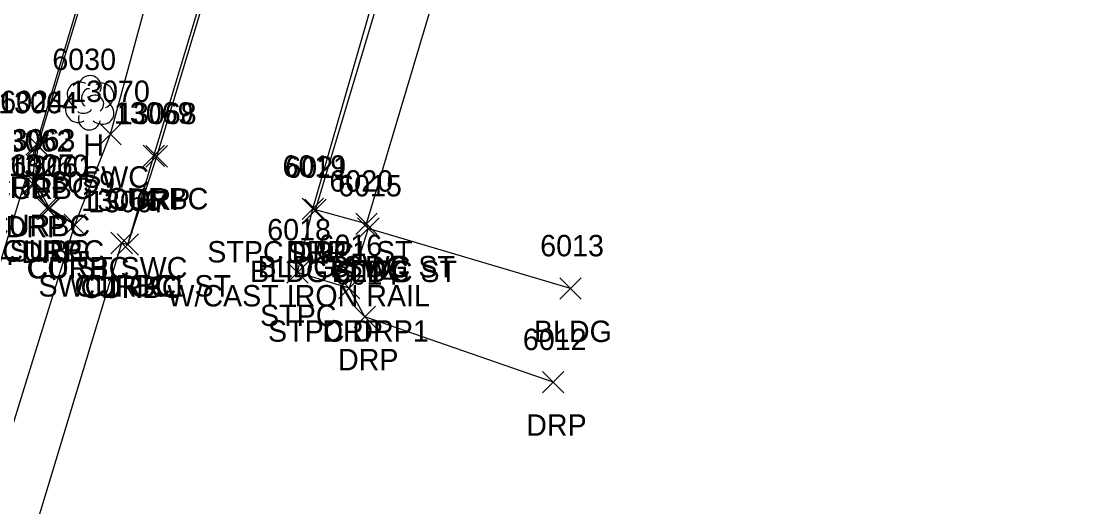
# Model space of a CAD drawing. Extents: x 1462089 to 1464015, y 730534 to 736144.
# Drawn here: x 1462484 to 1462582.3, y 730885.2 to 730930.6 of the extents above; entities that cross this region are included whole.
import ezdxf

# ---------------------------------------------------------------- set-up
doc = ezdxf.new("R2010")
doc.units = 0
for name, color, linetype in [('L_A', 7, 'Continuous'), ('L_I', 7, 'Continuous'), ('L_TIC', 7, 'Continuous'), ('LBC', 7, 'Continuous'), ('LBF', 7, 'Continuous'), ('LTD', 7, 'Continuous'), ('P_A', 7, 'Continuous'), ('P_I', 7, 'Continuous'), ('P_TIC', 7, 'Continuous'), ('PET', 7, 'Continuous'), ('R_A', 7, 'Continuous'), ('R_C', 7, 'Continuous'), ('R_I', 7, 'Continuous'), ('R_TIC', 7, 'Continuous'), ('RC', 7, 'Continuous'), ('RDP', 7, 'Continuous'), ('RSW', 7, 'Continuous'), ('U_A', 7, 'Continuous'), ('U_I', 7, 'Continuous'), ('U_TIC', 7, 'Continuous')]:
    doc.layers.add(name, color=color, linetype=linetype)

msp = doc.modelspace()

# ---------------------------------------------------------------- linework, layer by layer
at = {"layer": 'L_TIC'}
for points in [[(1462510.272, 730912.038), (1462512.272, 730914.038)], [(1462512.272, 730912.038), (1462510.272, 730914.038)], [(1462515.298, 730910.649), (1462517.298, 730912.649)], [(1462517.298, 730910.649), (1462515.298, 730912.649)], [(1462515.458, 730910.205), (1462517.458, 730912.205)], [(1462517.458, 730910.205), (1462515.458, 730912.205)], [(1462515.458, 730910.205), (1462517.458, 730912.205)], [(1462517.458, 730910.205), (1462515.458, 730912.205)], [(1462508.84, 730906.104), (1462510.84, 730908.104)], [(1462510.84, 730906.104), (1462508.84, 730908.104)], [(1462513.683, 730904.64), (1462515.683, 730906.64)], [(1462515.683, 730904.64), (1462513.683, 730906.64)], [(1462534.326, 730904.613), (1462536.326, 730906.613)], [(1462536.326, 730904.613), (1462534.326, 730906.613)]]:
    msp.add_lwpolyline(points, dxfattribs=at)
at = {"layer": 'LBC'}
msp.add_lwpolyline([(1462535.326, 730905.613), (1462516.458, 730911.205), (1462516.298, 730911.649), (1462524.384, 730938.78), (1462533.922, 730970.766), (1462531.573, 730971.668), (1462537.417, 730991.493), (1462540.657, 731001.604), (1462560.129, 730995.57)], dxfattribs=at)
at = {"layer": 'LBF'}
msp.add_lwpolyline([(1462516.458, 730911.205), (1462514.683, 730905.64), (1462509.84, 730907.104), (1462511.272, 730913.038)], dxfattribs=at)
at = {"layer": 'LTD'}
msp.add_line((1462490.429, 730922.994), (1462490.429, 730922.994), dxfattribs=at)
msp.add_line((1462490.429, 730922.994), (1462490.429, 730922.994), dxfattribs=at)
msp.add_arc((1462490.476, 730924.428), 1.047, 335.52715, 180.95627, dxfattribs=at)
for centre, major_axis, ratio, start_param, end_param in [((1462489.638, 730923.661), (1.21, -0.512), 0.895232, 1.570796, 4.712389), ((1462490.221, 730923.452), (-0.208, -0.792), 0.645439, 3.141593, 6.283185), ((1462491.471, 730923.578), (-1.141, -0.483), 0.949671, 1.570796, 4.712389), ((1462489.346, 730922.286), (0.584, -1.042), 0.959034, 3.141593, 6.283185), ((1462490.93, 730922.827), (-0.5, 0.667), 0.989748, 3.141593, 6.283185), ((1462491.43, 730922.161), (-1.09, 0.792), 0.841452, 1.570796, 4.712389), ((1462489.971, 730922.244), (-0.625, -0.083), 0.423636, 0, 3.141593), ((1462490.43, 730921.494), (0.265, 1.061), 0.942809, 1.570796, 4.712389)]:
    msp.add_ellipse(centre, major_axis=major_axis, ratio=ratio, start_param=start_param, end_param=end_param, dxfattribs=at)
at = {"layer": 'P_TIC'}
for points in [[(1462484.477, 730918.066), (1462486.477, 730920.066)], [(1462486.477, 730918.066), (1462484.477, 730920.066)]]:
    msp.add_lwpolyline(points, dxfattribs=at)
at = {"layer": 'PET'}
msp.add_lwpolyline([(1462373.445, 730550.573), (1462388.309, 730598.891), (1462401.963, 730641.783), (1462433.168, 730744.632), (1462438.196, 730760.147), (1462452.976, 730810.554), (1462463.625, 730846.159), (1462471.864, 730873.588), (1462478.576, 730896.599), (1462485.477, 730919.066), (1462495.517, 730952.686), (1462508.095, 730994.119), (1462517.419, 731025.054), (1462526.796, 731054.959), (1462537.856, 731087.551), (1462549.797, 731117.253), (1462553.734, 731129.646)], dxfattribs=at)
at = {"layer": 'R_TIC'}
for points in [[(1462491.382, 730919.018), (1462493.382, 730921.018)], [(1462493.382, 730919.018), (1462491.382, 730921.018)], [(1462484.617, 730917.96), (1462486.617, 730919.96)], [(1462486.617, 730917.96), (1462484.617, 730919.96)], [(1462495.432, 730916.994), (1462497.432, 730918.994)], [(1462497.432, 730916.994), (1462495.432, 730918.994)], [(1462495.703, 730916.944), (1462497.703, 730918.944)], [(1462497.703, 730916.944), (1462495.703, 730918.944)], [(1462484.115, 730914.389), (1462486.115, 730916.389)], [(1462486.115, 730914.389), (1462484.115, 730916.389)], [(1462484.39, 730914.486), (1462486.39, 730916.486)], [(1462486.39, 730914.486), (1462484.39, 730916.486)], [(1462485.579, 730912.004), (1462487.579, 730914.004)], [(1462487.579, 730912.004), (1462485.579, 730914.004)], [(1462485.707, 730912.107), (1462487.707, 730914.107)], [(1462487.707, 730912.107), (1462485.707, 730914.107)], [(1462510.272, 730912.038), (1462512.272, 730914.038)], [(1462512.272, 730912.038), (1462510.272, 730914.038)], [(1462510.522, 730911.936), (1462512.522, 730913.936)], [(1462512.522, 730911.936), (1462510.522, 730913.936)], [(1462488.057, 730910.55), (1462490.057, 730912.55)], [(1462490.057, 730910.55), (1462488.057, 730912.55)], [(1462488.057, 730910.55), (1462490.057, 730912.55)], [(1462490.057, 730910.55), (1462488.057, 730912.55)], [(1462488.057, 730910.55), (1462490.057, 730912.55)], [(1462490.057, 730910.55), (1462488.057, 730912.55)], [(1462515.298, 730910.649), (1462517.298, 730912.649)], [(1462517.298, 730910.649), (1462515.298, 730912.649)], [(1462492.434, 730908.857), (1462494.434, 730910.857)], [(1462494.434, 730908.857), (1462492.434, 730910.857)], [(1462492.434, 730908.857), (1462494.434, 730910.857)], [(1462494.434, 730908.857), (1462492.434, 730910.857)], [(1462493.015, 730908.723), (1462495.015, 730910.723)], [(1462495.015, 730908.723), (1462493.015, 730910.723)], [(1462493.015, 730908.723), (1462495.015, 730910.723)], [(1462495.015, 730908.723), (1462493.015, 730910.723)], [(1462513.683, 730904.64), (1462515.683, 730906.64)], [(1462515.683, 730904.64), (1462513.683, 730906.64)], [(1462515.143, 730901.972), (1462517.143, 730903.972)], [(1462517.143, 730901.972), (1462515.143, 730903.972)], [(1462532.706, 730895.863), (1462534.706, 730897.863)], [(1462534.706, 730895.863), (1462532.706, 730897.863)]]:
    msp.add_lwpolyline(points, dxfattribs=at)
at = {"layer": 'RC'}
for points in [[(1462493.434, 730909.857), (1462494.015, 730909.723), (1462496.432, 730917.994), (1462504.726, 730945.42), (1462507.323, 730953.276), (1462506.792, 730953.446)], [(1462485.617, 730918.96), (1462495.777, 730952.455)], [(1462489.057, 730911.55), (1462486.707, 730913.107), (1462485.39, 730915.486), (1462485.617, 730918.96)]]:
    msp.add_lwpolyline(points, dxfattribs=at)
at = {"layer": 'RDP'}
for points in [[(1462494.015, 730909.723), (1462496.703, 730917.944), (1462504.987, 730945.36), (1462507.323, 730953.276)], [(1462511.272, 730913.038), (1462518.156, 730936.915)], [(1462485.115, 730915.389), (1462485.477, 730919.066)], [(1462489.057, 730911.55), (1462486.579, 730913.004), (1462485.115, 730915.389)], [(1462533.706, 730896.863), (1462516.143, 730902.972), (1462514.683, 730905.64)]]:
    msp.add_lwpolyline(points, dxfattribs=at)
at = {"layer": 'RSW'}
for points in [[(1462478.395, 730877.187), (1462489.057, 730911.55), (1462492.382, 730920.018), (1462499.727, 730947.071), (1462502.259, 730954.951), (1462512.149, 730987.955), (1462515.322, 730997.987), (1462519.414, 731012.011), (1462525.511, 731020.015), (1462536.508, 731054.258), (1462538.499, 731059.538), (1462541.2, 731067.117), (1462544.888, 731076.412), (1462544.393, 731076.888), (1462551.37, 731081.195), (1462551.654, 731080.58), (1462553.328, 731081.433), (1462557.626, 731083.23), (1462562.482, 731084.757), (1462582.337, 731080.557)], [(1462516.298, 730911.649), (1462511.522, 730912.936), (1462519.579, 730939.815), (1462525.971, 730961.134), (1462527.754, 730967.679), (1462524.542, 730968.683), (1462526.188, 730974.24), (1462529.027, 730983.662), (1462525.352, 730982.5)], [(1462415.196, 730659.689), (1462417.674, 730664.088), (1462425.293, 730676.369), (1462427.816, 730683.782), (1462442.002, 730729.636), (1462442.779, 730732.808), (1462445.728, 730742.244), (1462455.055, 730768.12), (1462467.301, 730808.318), (1462474.256, 730831.161), (1462480.008, 730860.315), (1462483.021, 730875.428), (1462493.434, 730909.857)]]:
    msp.add_lwpolyline(points, dxfattribs=at)
at = {"layer": 'U_TIC'}
for points in [[(1462485.44, 730912.123), (1462487.44, 730914.123)], [(1462487.44, 730912.123), (1462485.44, 730914.123)]]:
    msp.add_lwpolyline(points, dxfattribs=at)

# ---------------------------------------------------------------- texts
at = {"layer": 'L_A'}
for s, p in [('H', (1462489.863, 730917.994)), ('STPC DRP1 ST', (1462501.422, 730908.038)), ('BLDG', (1462512.888, 730906.649)), ('BLDG STPC ST', (1462505.426, 730906.205)), ('BLDG', (1462513.048, 730906.205)), ('STPC', (1462506.352, 730902.104)), ('STPC DRP1', (1462507.093, 730900.64)), ('BLDG', (1462531.916, 730900.613))]:
    msp.add_text(s, height=2, dxfattribs=at).set_placement(p)
at = {"layer": 'L_I'}
for s, p in [('6030', (1462486.957, 730925.994)), ('6019', (1462508.445, 730916.038)), ('6020', (1462512.825, 730914.649)), ('6015', (1462513.639, 730914.205)), ('6015', (1462513.639, 730914.205)), ('6018', (1462507.021, 730910.104)), ('6016', (1462511.809, 730908.64)), ('6013', (1462532.507, 730908.613))]:
    msp.add_text(s, height=2, dxfattribs=at).set_placement(p)
at = {"layer": 'P_A'}
msp.add_text('RDP', height=2, dxfattribs=at).set_placement((1462482.965, 730914.066))
at = {"layer": 'P_I'}
msp.add_text('6024', height=2, dxfattribs=at).set_placement((1462482.091, 730922.066))
at = {"layer": 'R_A'}
for s, p in [('SWC', (1462489.744, 730915.018)), ('CURBC', (1462481.199, 730913.96)), ('CURBC', (1462492.014, 730912.994)), ('DRP', (1462494.191, 730912.944)), ('CURBC', (1462480.973, 730910.486)), ('DRP', (1462482.603, 730910.389)), ('CURBC', (1462482.29, 730908.107)), ('DRP', (1462484.067, 730908.004)), ('DRP', (1462508.76, 730908.038)), ('SWC', (1462508.885, 730907.936)), ('DRP ST CC ST SWC', (1462474.01, 730906.55)), ('CURBC', (1462484.64, 730906.55)), ('DRP', (1462486.545, 730906.55)), ('BLDG SWC ST', (1462506.117, 730906.649)), ('SWC1 CC1 ST', (1462485.663, 730904.857)), ('CURBC', (1462489.017, 730904.857)), ('CURBC', (1462489.598, 730904.723)), ('DRP', (1462491.503, 730904.723)), ('DRP', (1462512.171, 730900.64)), ('DRP', (1462513.631, 730897.972)), ('DRP', (1462531.195, 730891.863))]:
    msp.add_text(s, height=2, dxfattribs=at).set_placement(p)
at = {"layer": 'R_C'}
msp.add_text('W/CAST IRON RAIL', height=2, dxfattribs=at).set_placement((1462497.696, 730903.936))
at = {"layer": 'R_I'}
for s, p in [('13070', (1462488.626, 730923.018)), ('13064', (1462481.9, 730921.96)), ('13069', (1462492.707, 730920.994)), ('13068', (1462492.987, 730920.944)), ('13062', (1462481.399, 730918.389)), ('13063', (1462481.674, 730918.486)), ('13060', (1462482.904, 730916.107)), ('13061', (1462483.429, 730916.004)), ('6019', (1462508.445, 730916.038)), ('6021', (1462508.704, 730915.936)), ('13059', (1462485.38, 730914.55)), ('13059', (1462485.38, 730914.55)), ('13059', (1462485.38, 730914.55)), ('6020', (1462512.825, 730914.649)), ('13066', (1462489.663, 730912.857)), ('13066', (1462489.663, 730912.857)), ('13067', (1462490.299, 730912.723)), ('13067', (1462490.299, 730912.723)), ('6016', (1462511.809, 730908.64)), ('6014', (1462513.324, 730905.972)), ('6012', (1462530.888, 730899.863))]:
    msp.add_text(s, height=2, dxfattribs=at).set_placement(p)
at = {"layer": 'U_A'}
msp.add_text('SUBG', height=2, dxfattribs=at).set_placement((1462482.967, 730908.123))
at = {"layer": 'U_I'}
msp.add_text('6027', height=2, dxfattribs=at).set_placement((1462483.054, 730916.123))

doc.saveas('drawing.dxf')
